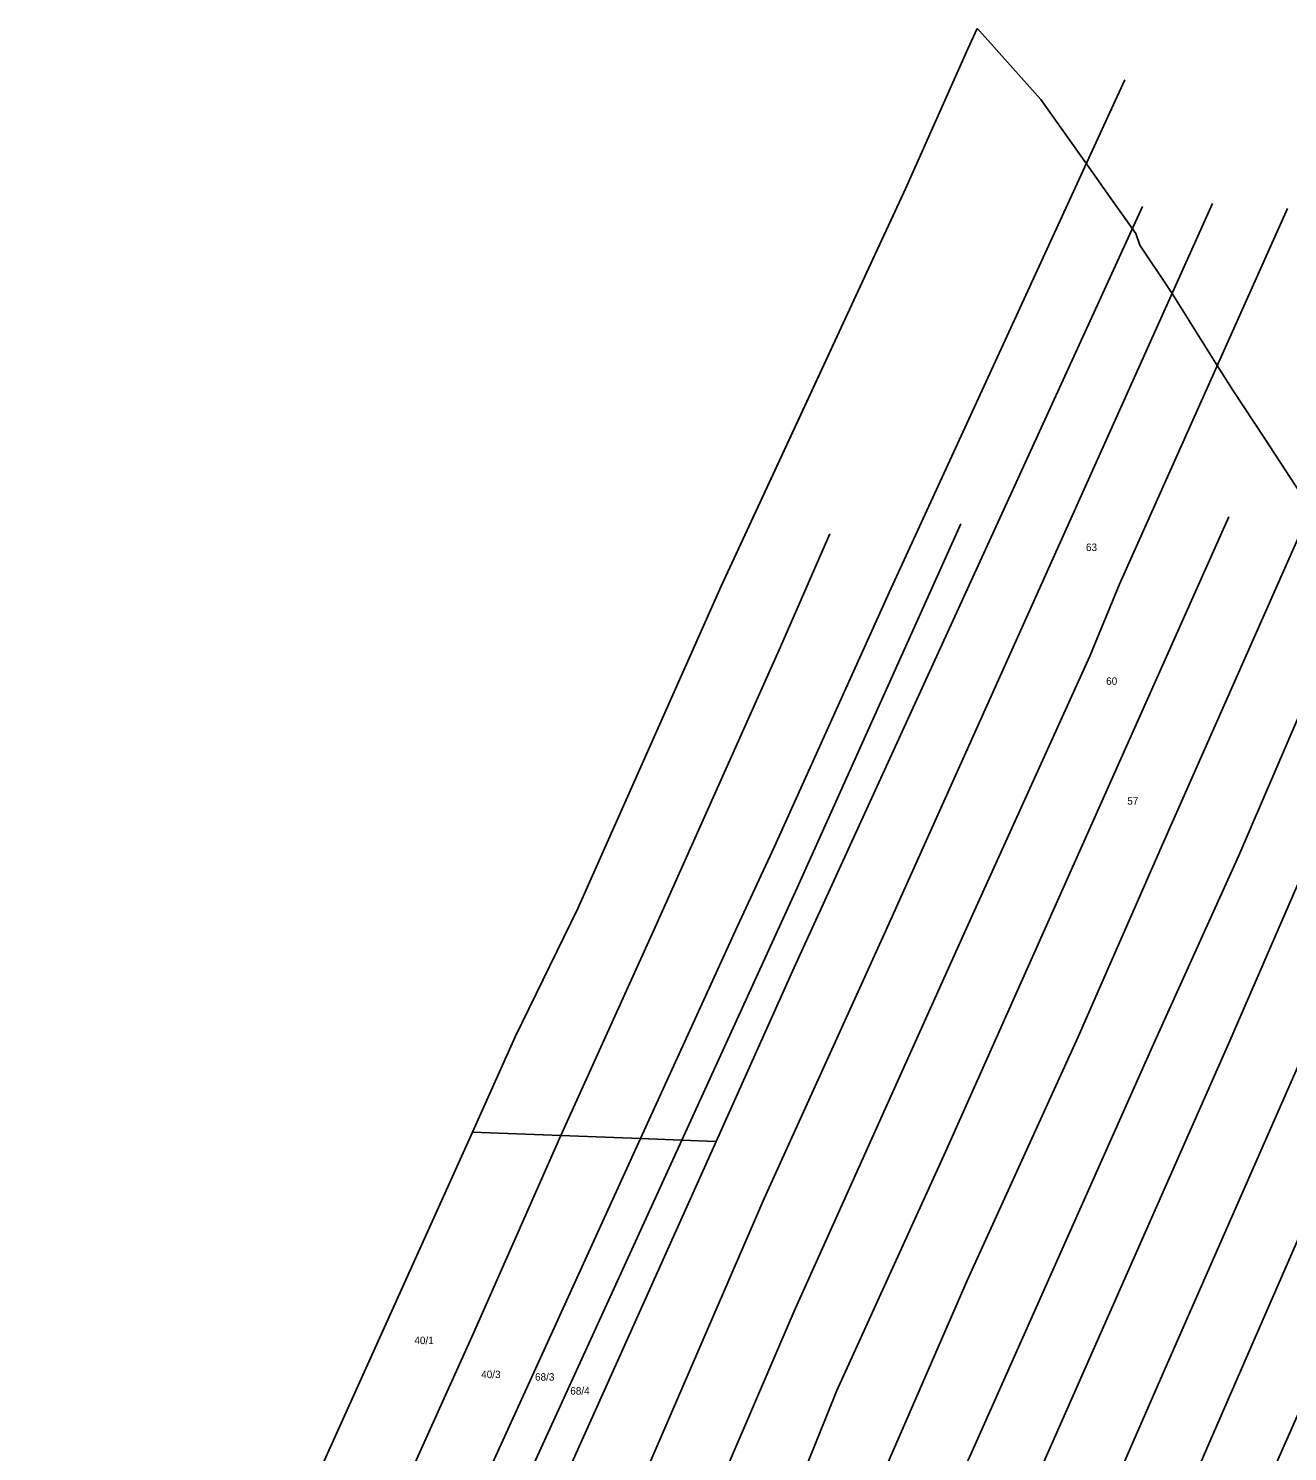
# Model space of a CAD drawing. Extents: x -747333 to -745433, y -1133152 to -1130600.
# Drawn here: x -746319.4 to -746032, y -1130924.3 to -1130599.6 of the extents above; entities that cross this region are included whole.
import ezdxf

# ---------------------------------------------------------------- set-up
doc = ezdxf.new("R2010")
doc.units = 0
for name, color, linetype in [('Vrstva 13', 7, 'Continuous'), ('Vrstva 18', 7, 'Continuous'), ('Vrstva 52', 7, 'Continuous'), ('Vrstva 6', 7, 'Continuous')]:
    doc.layers.add(name, color=color, linetype=linetype)

msp = doc.modelspace()

# ---------------------------------------------------------------- linework, layer by layer
at = {"layer": 'Vrstva 13'}
for points in [[(-746161.29, -1130726.79), (-746119.21, -1130636.12)], [(-746193.97, -1130800.38), (-746161.29, -1130726.79)], [(-746208.27, -1130829.69), (-746193.97, -1130800.38)], [(-746218.07, -1130851.43), (-746208.27, -1130829.69)], [(-746257.43, -1130938.7), (-746218.07, -1130851.43)]]:
    msp.add_lwpolyline(points, dxfattribs=at)
at = {"layer": 'Vrstva 52'}
for points in [[(-746356.02, -1130965.68), (-746316.94, -1130953.92), (-746289.5, -1130941.1), (-746276.05, -1130940.66), (-746261.76, -1130941.15), (-746258.58, -1130941.26), (-746257.43, -1130938.7), (-746239.27, -1130898.44), (-746218.07, -1130851.43), (-746208.27, -1130829.69), (-746193.97, -1130800.38), (-746161.29, -1130726.79), (-746142.44, -1130686.18), (-746137.11, -1130674.69), (-746133.46, -1130666.82), (-746124.71, -1130647.97), (-746122.04, -1130642.23), (-746119.21, -1130636.12), (-746104.94, -1130604.23), (-746102.85, -1130599.56)], [(-746102.85, -1130599.56), (-746102.31, -1130600.13), (-746089.61, -1130614.31), (-746088.31, -1130615.75), (-746077.92, -1130630.43), (-746072.63, -1130637.89), (-746067.41, -1130645.27), (-746066.62, -1130646.38), (-746065.75, -1130649), (-746058.94, -1130659.12), (-746058.36, -1130660.04), (-746048.05, -1130676.47), (-746044.5, -1130682.13), (-746037.3, -1130693.06), (-746026.66, -1130709.22)]]:
    msp.add_lwpolyline(points, dxfattribs=at)
at = {"layer": 'Vrstva 6'}
for points in [[(-746069.12, -1130611.3), (-746122.54, -1130727.42)], [(-746144.6, -1130813.87), (-746065.09, -1130640.2)], [(-746123.64, -1130805.21), (-746049.14, -1130639.52)], [(-746070.33, -1130726.35), (-746032.05, -1130640.66)], [(-746060.33, -1130785.21), (-746004.63, -1130659.52)], [(-746106.6, -1130712.61), (-746143.96, -1130795.68)], [(-746045.43, -1130711.03), (-746110.07, -1130855.92)], [(-746136.44, -1130714.88), (-746147.72, -1130740.64)], [(-746045.19, -1130830.57), (-745995.29, -1130715.64)], [(-746122.54, -1130727.42), (-746149.09, -1130786.22)], [(-746077.16, -1130742.76), (-746070.33, -1130726.35)], [(-746043.13, -1130788.29), (-746021.26, -1130737.58)], [(-746147.72, -1130740.64), (-746175.97, -1130803.77)], [(-746105.64, -1130805.67), (-746077.16, -1130742.76)], [(-746045.88, -1130913.08), (-745982.43, -1130767.68)], [(-746149.09, -1130786.22), (-746157.63, -1130804.57)], [(-746079.82, -1130829.66), (-746060.33, -1130785.21)], [(-746062.62, -1130831.37), (-746043.13, -1130788.29)], [(-746143.96, -1130795.68), (-746170.29, -1130853.24)], [(-746175.97, -1130803.77), (-746197.84, -1130852.2)], [(-746179.66, -1130852.89), (-746157.63, -1130804.57)], [(-746151.44, -1130866.52), (-746123.64, -1130805.21)], [(-746144.6, -1130892.27), (-746105.64, -1130805.67)], [(-746016.83, -1130807.21), (-746059.9, -1130905.32)], [(-746162.43, -1130853.54), (-746144.6, -1130813.87)], [(-746105.11, -1130885.27), (-746079.82, -1130829.66)], [(-746105.23, -1130926.97), (-746062.62, -1130831.37)], [(-746088.14, -1130927.89), (-746045.19, -1130830.57)], [(-745994.18, -1130835.79), (-746034.56, -1130926.83)], [(-746197.84, -1130852.2), (-746218.07, -1130851.43)], [(-746217.8, -1130897.25), (-746197.84, -1130852.2)], [(-746179.66, -1130852.89), (-746197.84, -1130852.2)], [(-746214.66, -1130929.63), (-746179.66, -1130852.89)], [(-746207.49, -1130953.81), (-746162.43, -1130853.54)], [(-746170.29, -1130853.24), (-746188.23, -1130892.48)], [(-746170.29, -1130853.24), (-746179.66, -1130852.89)], [(-746162.43, -1130853.54), (-746170.29, -1130853.24)], [(-746110.07, -1130855.92), (-746134.91, -1130910.39)], [(-746188.8, -1130952.9), (-746151.44, -1130866.52)], [(-746123.45, -1130927.43), (-746105.11, -1130885.27)], [(-746188.23, -1130892.48), (-746225.59, -1130974.19)], [(-746187.79, -1130992.68), (-746144.6, -1130892.27)], [(-746241.39, -1130949.57), (-746217.8, -1130897.25)], [(-746059.9, -1130905.32), (-746095.78, -1130987.36)], [(-746134.91, -1130910.39), (-746141.52, -1130926.8)], [(-746096.35, -1131029.25), (-746045.88, -1130913.08)]]:
    msp.add_lwpolyline(points, dxfattribs=at)

# ---------------------------------------------------------------- texts
at = {"layer": 'Vrstva 18'}
for s, p in [('63', (-746078.01, -1130718.8)), ('60', (-746073.4, -1130749.34)), ('57', (-746068.59, -1130776.68)), ('40/1', (-746231.3, -1130899.78)), ('40/3', (-746216.05, -1130907.53)), ('68/3', (-746203.77, -1130908.11)), ('68/4', (-746195.72, -1130911.3))]:
    msp.add_text(s, height=1.7, dxfattribs=at).set_placement(p)

doc.saveas('drawing.dxf')
